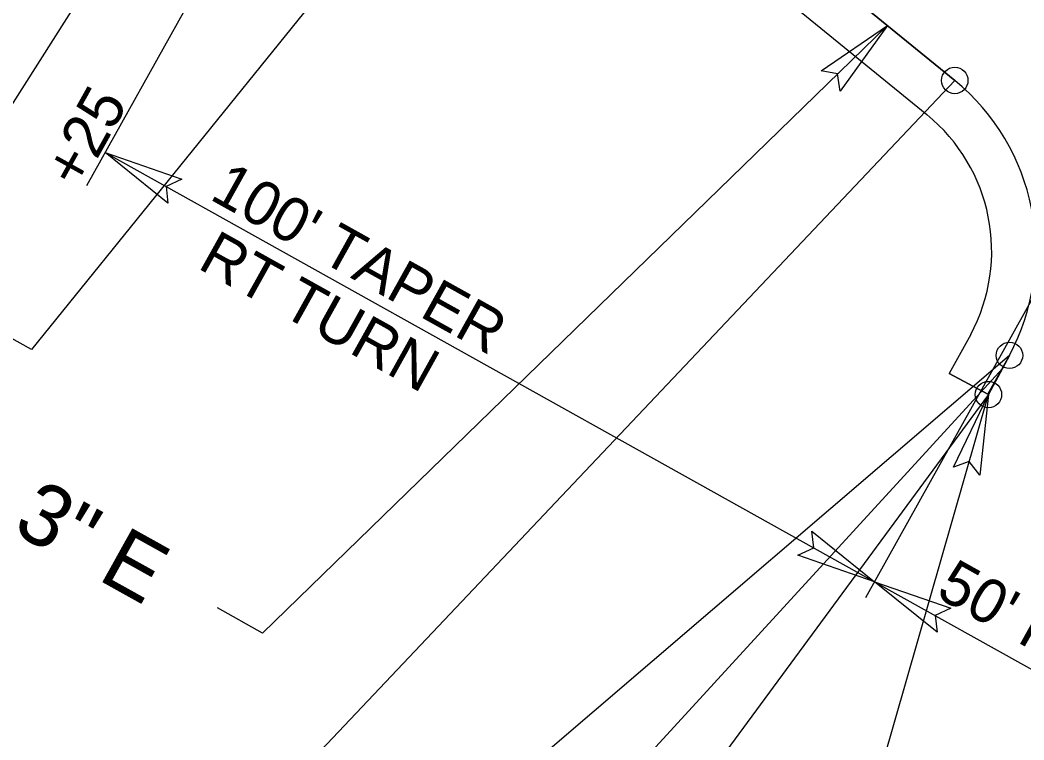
# Model space of a CAD drawing. Extents: x 1762196 to 1766326, y 709922 to 713142.
# Drawn here: x 1764499.2 to 1764613.1, y 710792.5 to 710874.2 of the extents above; entities that cross this region are included whole.
import ezdxf

# ---------------------------------------------------------------- set-up
doc = ezdxf.new("R2010")
doc.units = 0
for name, color, linetype in [('Pattern 1', 7, 'Continuous'), ('Pattern 2', 7, 'Continuous'), ('Prop Dimension', 7, 'Continuous'), ('Prop Horizontal Alignment', 7, 'Continuous'), ('Prop Horizontal Alignment Direction Label', 7, 'Continuous'), ('Prop Horizontal Alignment Station Label', 7, 'Continuous'), ('Prop Terminator CELL', 7, 'Continuous')]:
    doc.layers.add(name, color=color, linetype=linetype)

msp = doc.modelspace()

# ---------------------------------------------------------------- linework, layer by layer
at = {"layer": 'Pattern 1'}
for p, q in [((1764605.28, 710867.3), (1764557.01, 710906.71)), ((1764553.84, 710902.83), (1764602.12, 710863.42)), ((1764607.09, 710838.46), (1764604.63, 710834.05)), ((1764609.04, 710831.68), (1764611.49, 710836.1)), ((1764604.63, 710834.05), (1764609.04, 710831.68))]:
    msp.add_line(p, q, dxfattribs=at)
for radius in [25, 20]:
    msp.add_arc((1764589.47, 710847.93), radius, 331.7448, 50.7729, dxfattribs=at)
at = {"layer": 'Pattern 2'}
for p, q in [((1764557.01, 710906.71), (1764605.28, 710867.3)), ((1764553.84, 710902.83), (1764602.12, 710863.42)), ((1764607.09, 710838.46), (1764604.63, 710834.05)), ((1764611.49, 710836.1), (1764609.04, 710831.68)), ((1764609.04, 710831.68), (1764604.63, 710834.05))]:
    msp.add_line(p, q, dxfattribs=at)
for radius in [25, 20]:
    msp.add_arc((1764589.47, 710847.93), radius, 331.7448, 50.7729, dxfattribs=at)
at = {"layer": 'Prop Dimension'}
for p, q in [((1764506.74, 710855.37), (1764558.25, 710947.71)), ((1764595.17, 710808.63), (1764639.91, 710888.82)), ((1764508.83, 710859.13), (1764596.16, 710810.41)), ((1764586.94, 710754.42), (1764609.1, 710831.65)), ((1764596.16, 710810.41), (1764639.83, 710786.05))]:
    msp.add_line(p, q, dxfattribs=at)
at = {"layer": 'Prop Horizontal Alignment'}
for p, q in [((1764557.01, 710906.71), (1764605.28, 710867.3)), ((1764611.49, 710836.1), (1764609.1, 710831.65))]:
    msp.add_line(p, q, dxfattribs=at)
msp.add_arc((1764589.47, 710847.93), 25, 331.7448, 50.7729, dxfattribs=at)
at = {"layer": 'Prop Horizontal Alignment Station Label'}
for p, q in [((1764566.4, 710971.93), (1764496.28, 710861.52)), ((1764557.01, 710906.71), (1764500.44, 710836.76)), ((1764500.44, 710836.76), (1764393.94, 710896.06)), ((1764597.63, 710873.54), (1764526.69, 710804.58)), ((1764605.28, 710867.3), (1764509.01, 710765.62)), ((1764611.49, 710836.1), (1764511.41, 710750.42)), ((1764610.7, 710834.62), (1764510.14, 710724.96)), ((1764609.1, 710831.65), (1764506.66, 710692.45)), ((1764526.69, 710804.58), (1764521.58, 710807.43))]:
    msp.add_line(p, q, dxfattribs=at)
for centre in [(1764605.28, 710867.3), (1764611.49, 710836.1), (1764609.1, 710831.65)]:
    msp.add_circle(centre, 1.5, dxfattribs=at)
at = {"layer": 'Prop Terminator CELL'}
for points in [[(1764590.1, 710868.38), (1764597.63, 710873.54), (1764592.26, 710866.09), (1764591.97, 710868.04)], [(1764515.94, 710853.39), (1764508.83, 710859.13), (1764517.52, 710856.11), (1764515.73, 710855.28)], [(1764605.13, 710823.42), (1764609.1, 710831.65), (1764608.14, 710822.51), (1764606.92, 710824.05)], [(1764589.06, 710816.15), (1764596.16, 710810.41), (1764587.48, 710813.42), (1764589.27, 710814.26)], [(1764603.27, 710804.67), (1764596.16, 710810.41), (1764604.85, 710807.4), (1764603.06, 710806.56)]]:
    msp.add_lwpolyline(points, close=True, dxfattribs=at)

# ---------------------------------------------------------------- texts
at = {"layer": 'Prop Dimension'}
for s, rotation, p in [('+25', 60.8436, (1764505.93, 710854.79)), ("100' TAPER", 330.8436, (1764520.54, 710853.89)), ('RT TURN', 330.8436, (1764519.17, 710846.06)), ("50' FULL RT", 330.8436, (1764602.98, 710808.78))]:
    msp.add_text(s, height=5, rotation=rotation, dxfattribs=at).set_placement(p)
at = {"layer": 'Prop Horizontal Alignment Direction Label'}
msp.add_text('S 50%%d 46\' 22.3" E', height=7, rotation=330.8875, dxfattribs=at).set_placement((1764451.44, 710842.13))
at = {"layer": 'Prop Horizontal Alignment Station Label'}
msp.add_text('-TRAIL- PC Sta.  11+85.47', height=7, rotation=330.8875, dxfattribs=at).set_placement((1764404.37, 710825.8))

doc.saveas('drawing.dxf')
